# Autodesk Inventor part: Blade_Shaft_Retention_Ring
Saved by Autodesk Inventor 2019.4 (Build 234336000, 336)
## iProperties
Created: 2020-02
Part Number: Blade_Shaft_Retention_Ring
Material: Generic
Document SubType Name: Modeling
Designer: Administrator
Density: 1 g/cm^3
Appearance: Default
Title: Blade_Shaft_Retention_Ring v1
Author: Administrator
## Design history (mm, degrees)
feature "Body1"
body "Solid1"
